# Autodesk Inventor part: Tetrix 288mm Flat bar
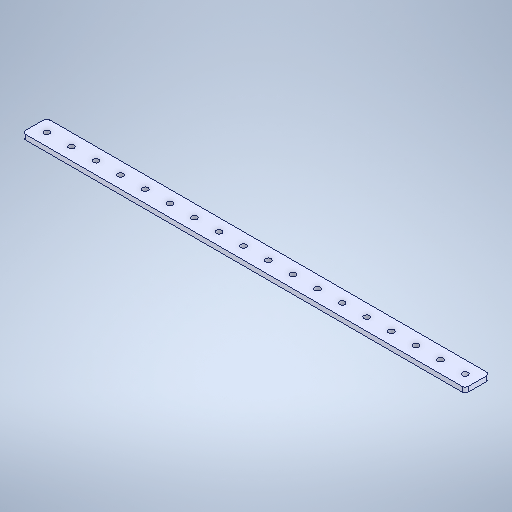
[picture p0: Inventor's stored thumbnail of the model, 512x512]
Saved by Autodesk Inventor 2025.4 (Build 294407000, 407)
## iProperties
Created: 2021-10
Part Number: Tetrix 288mm Flat bar
Material: Genérico
Document SubType Name: Modeling
Designer: usuario
Density: 1 g/cm^3
Appearance: Valor por defecto
Author: usuario
Sending System: SolidWorks 2016
Last Author: LENOVO
Last Saved: 2021-10-21
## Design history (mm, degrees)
feature "Boss-Extrude1"
node "Plane1"
node "Sólido1"
